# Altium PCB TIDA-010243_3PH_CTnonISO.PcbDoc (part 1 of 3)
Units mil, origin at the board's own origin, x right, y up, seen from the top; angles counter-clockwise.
Board outline 6131.89 x 7490.17 mil, 2 copper layers (Top Layer, Bottom Layer), stack 62 mil thick; 208 components, 218 nets, 747 pads, 147 vias.
Unrouted connection lines stored in the file: 258.
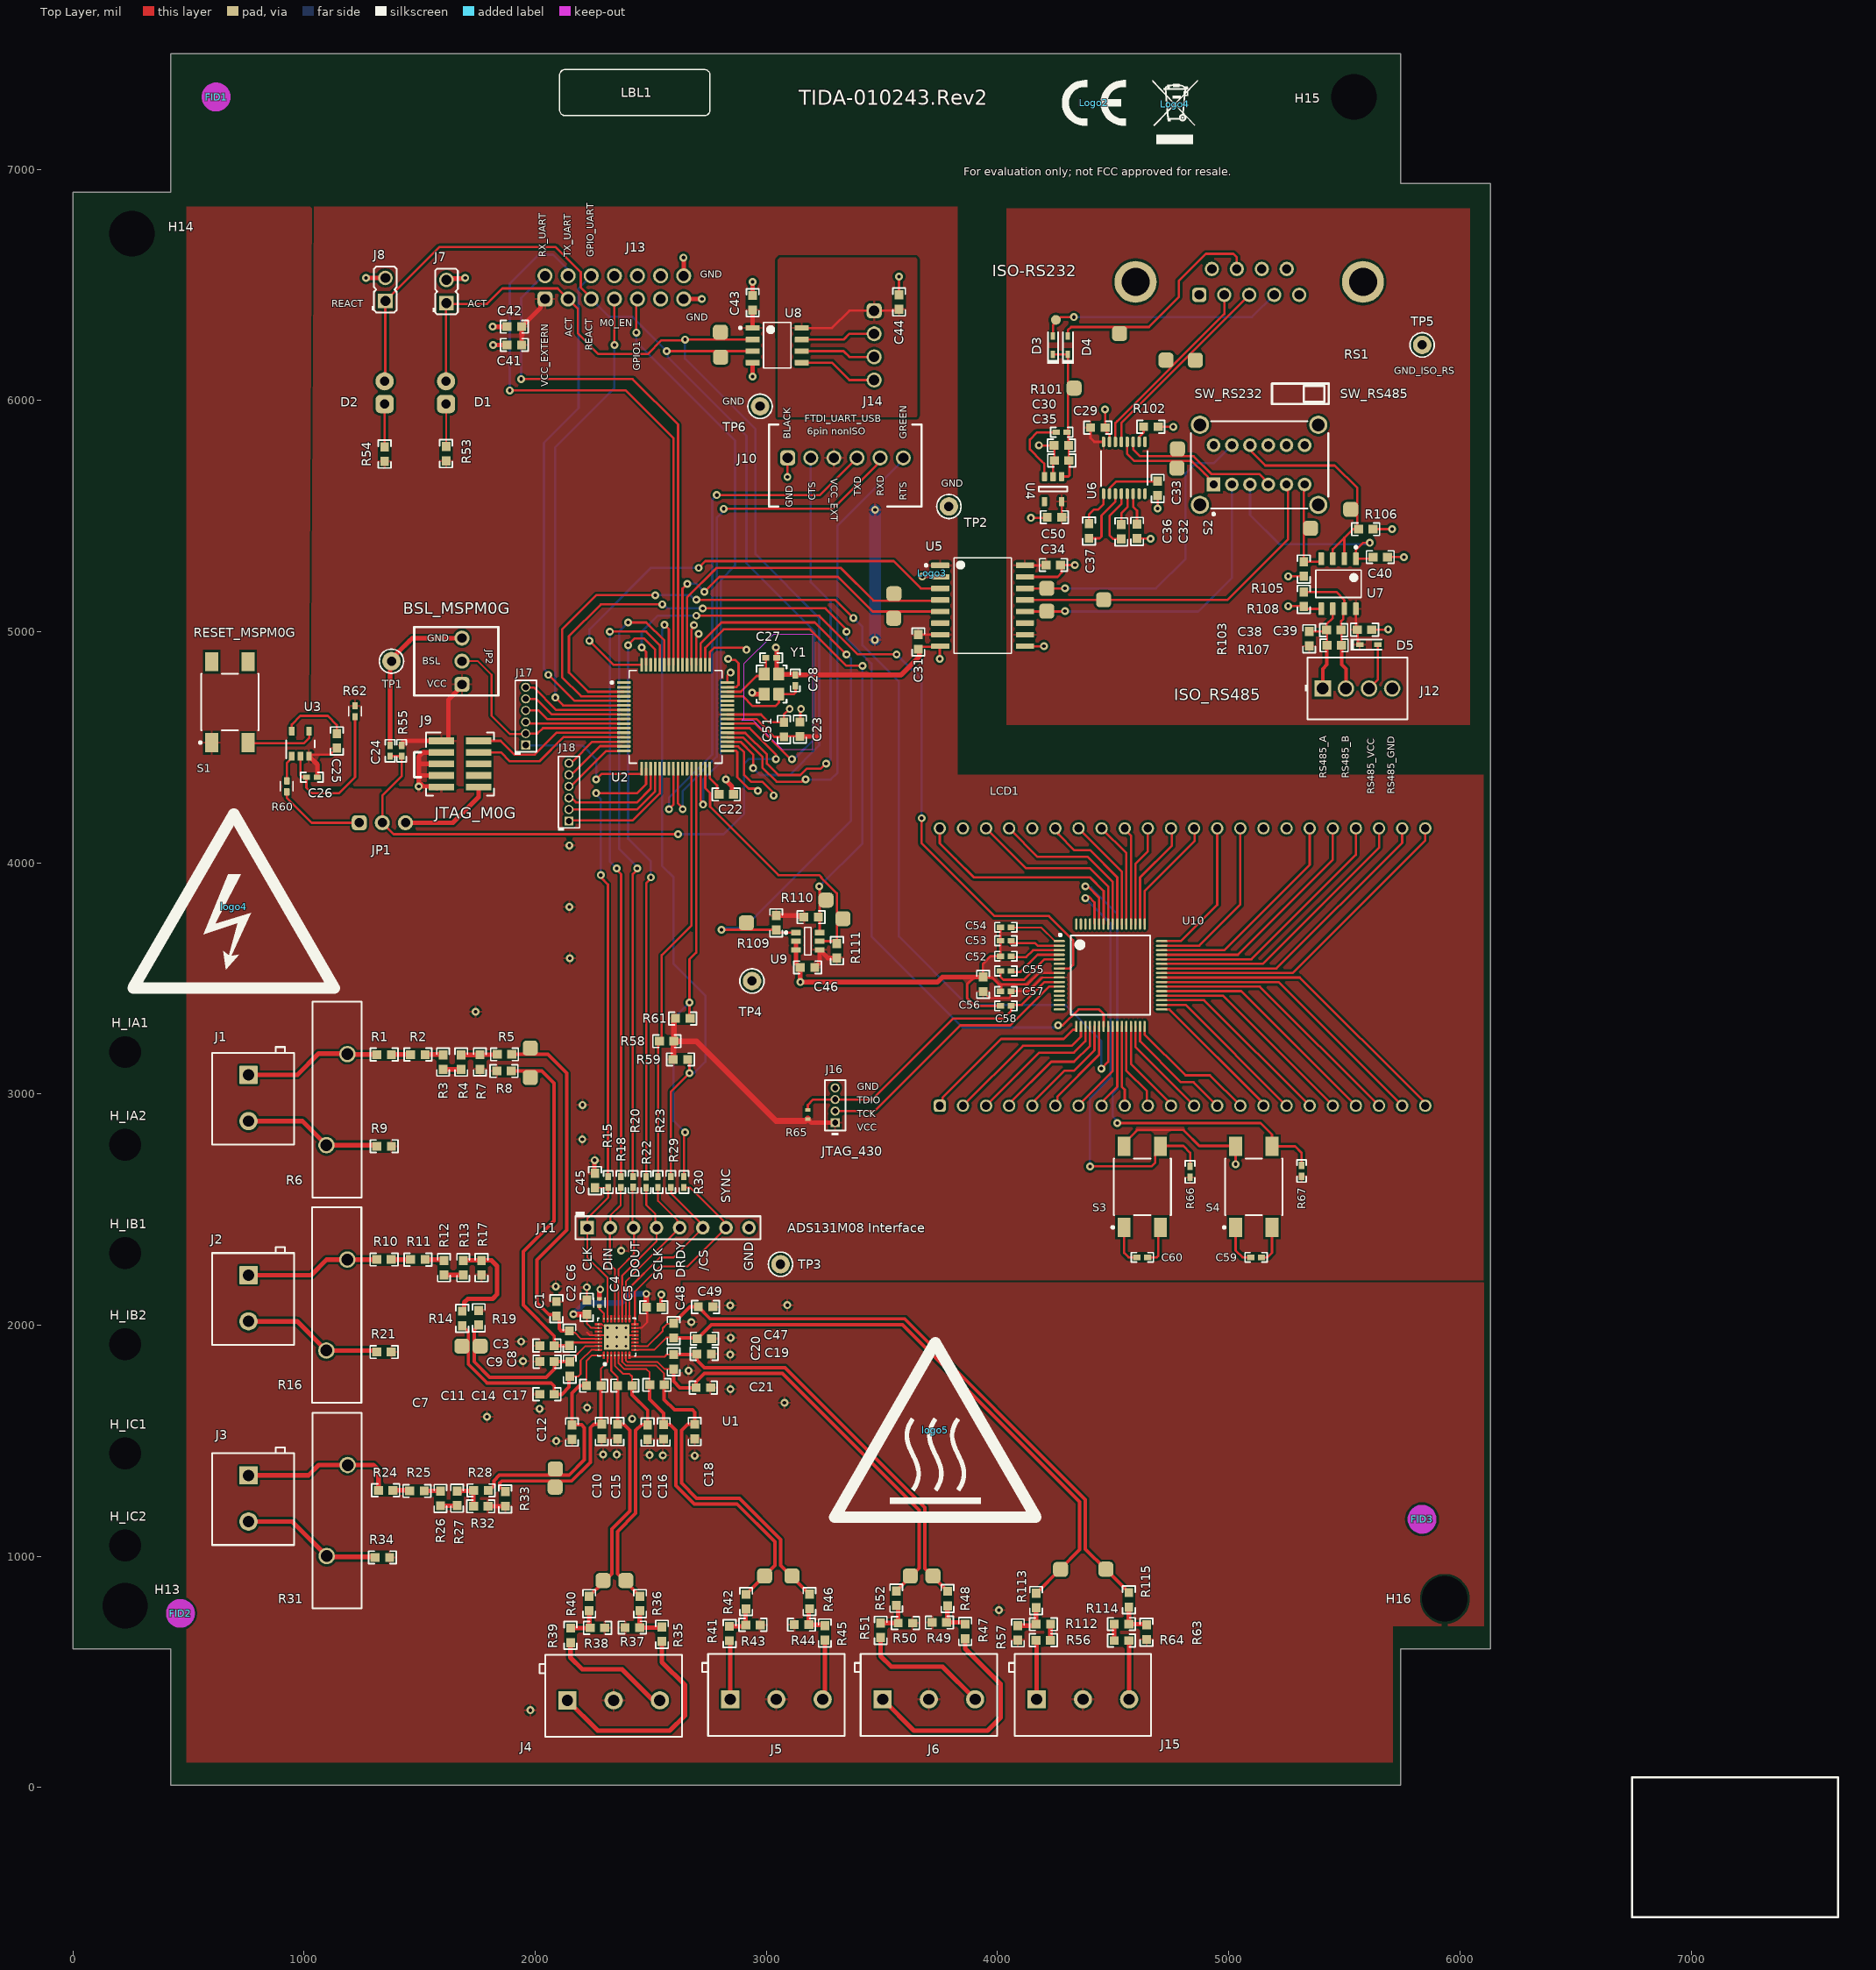
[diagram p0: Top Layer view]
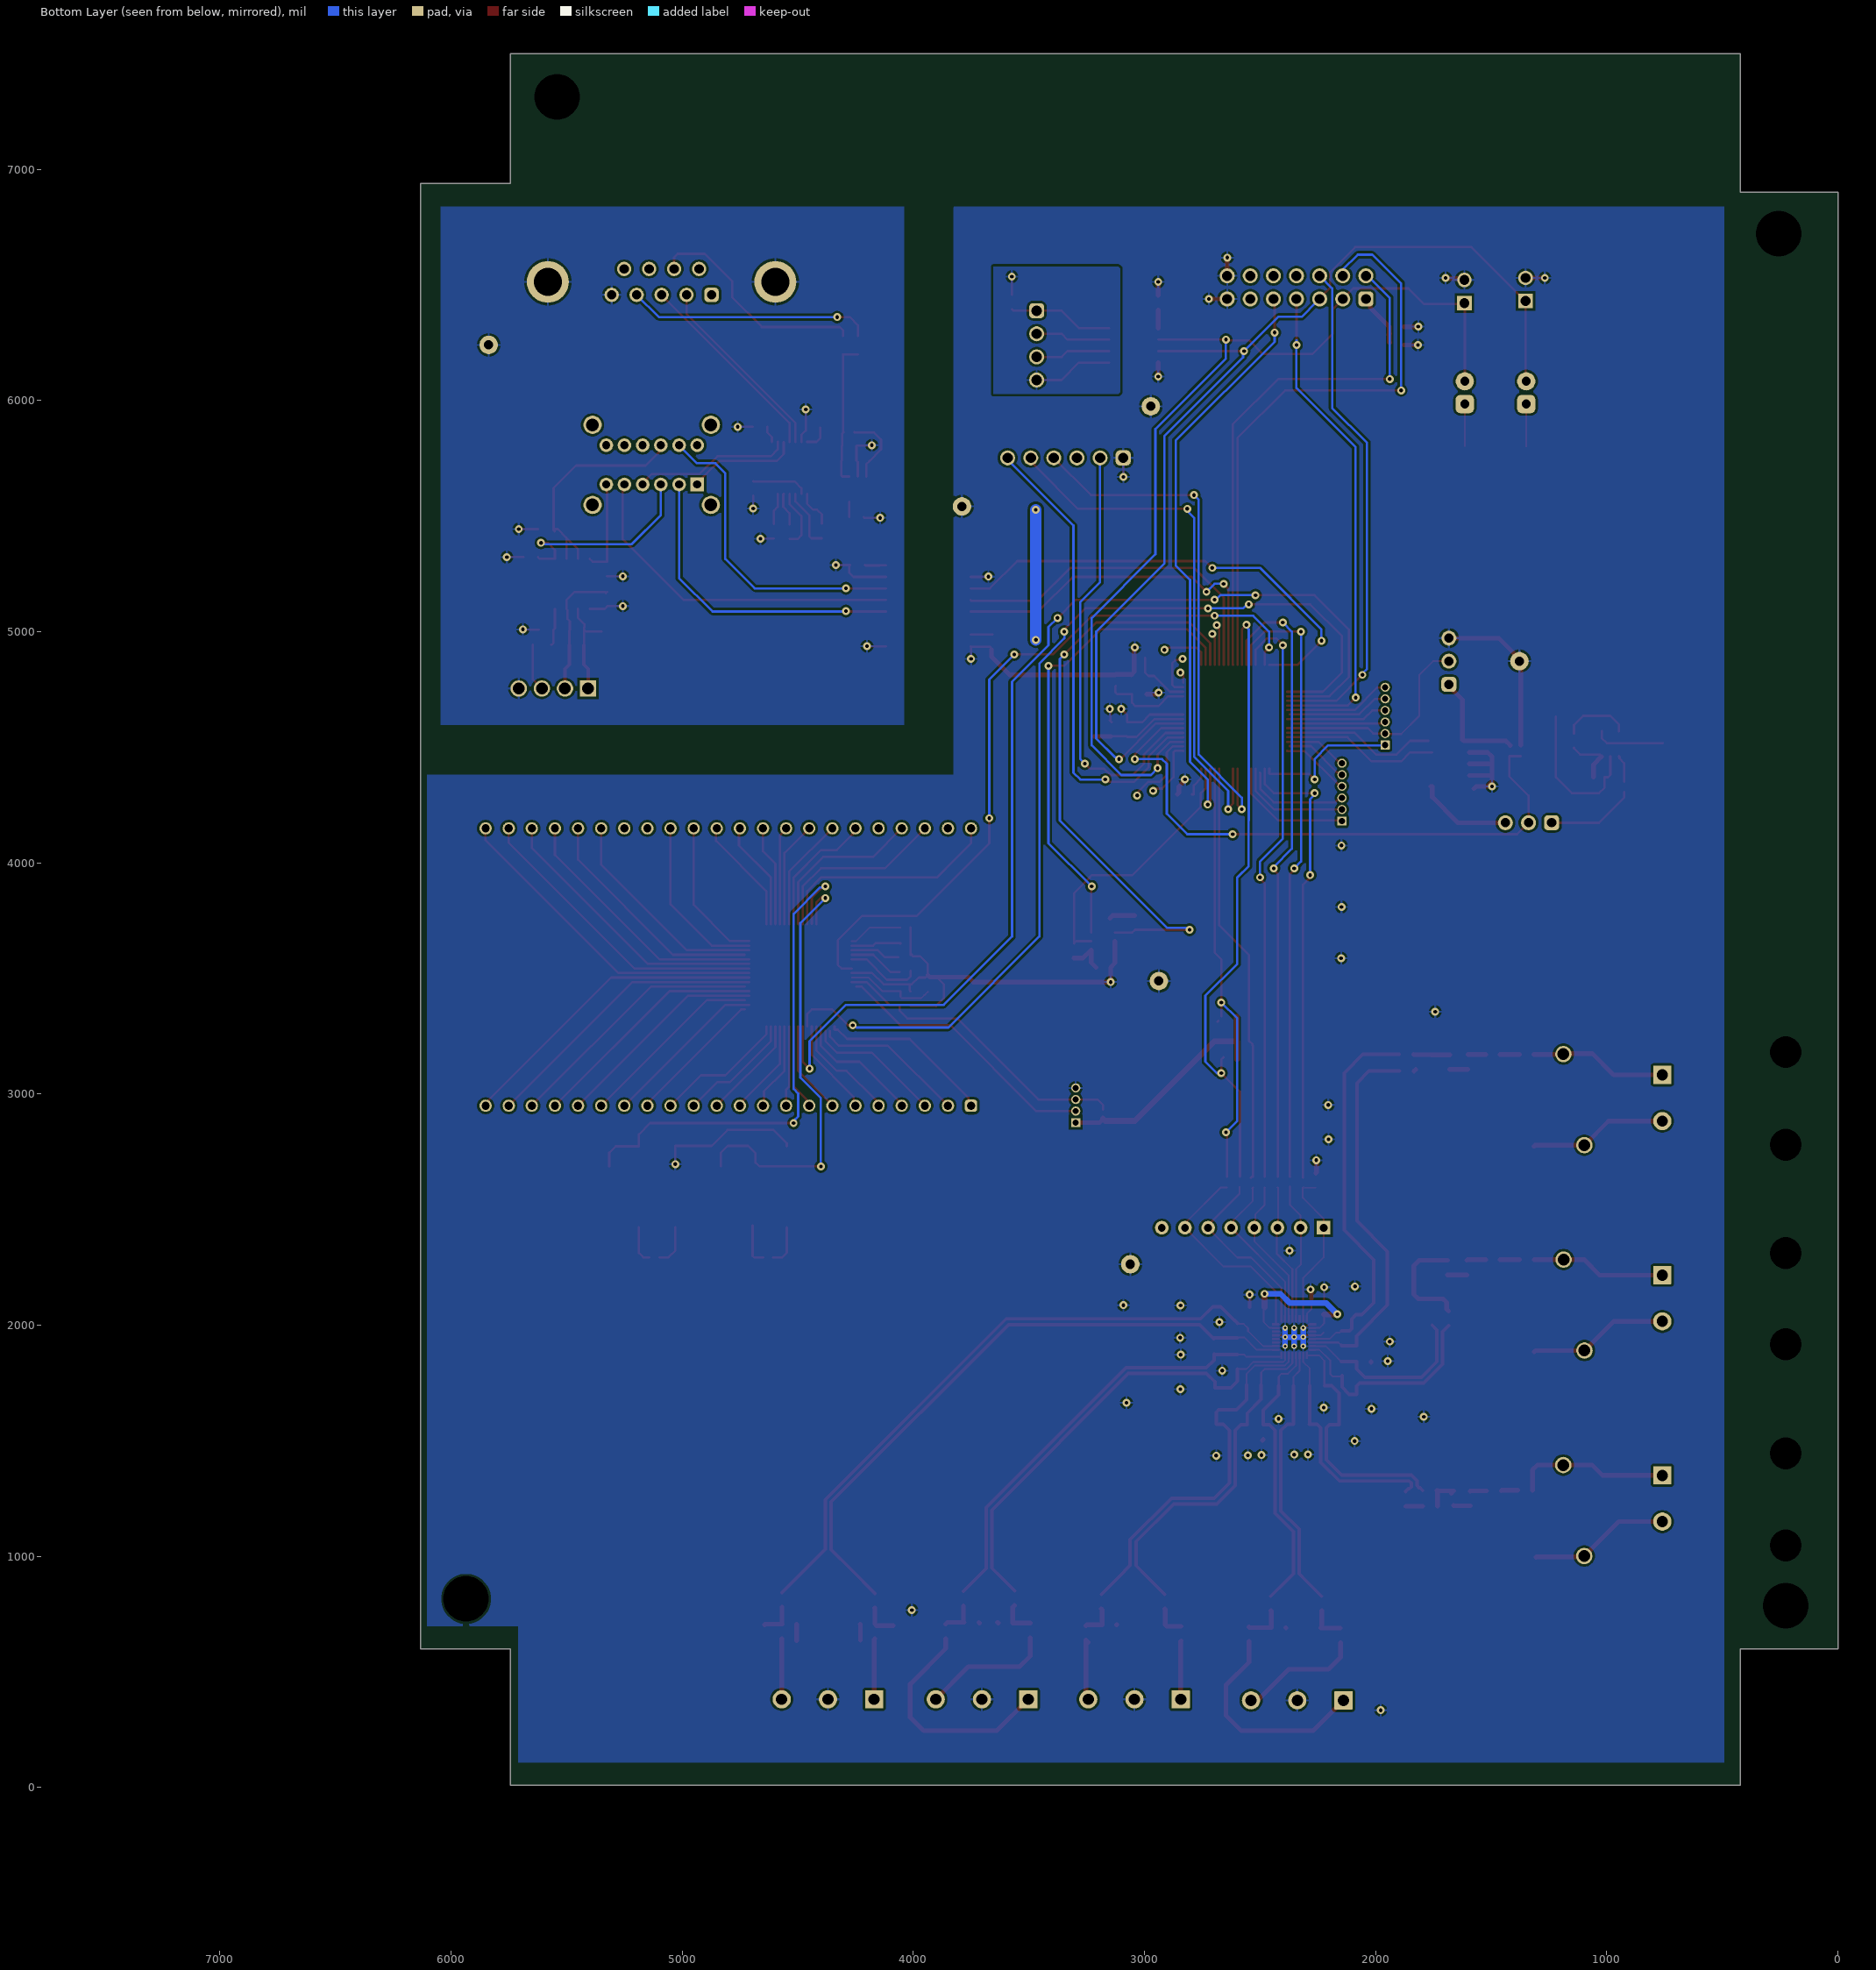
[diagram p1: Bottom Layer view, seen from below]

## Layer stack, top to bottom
Top Solder: solder mask 0.4, Solder Resist, Dk 3.5
Top Layer: signal copper 1.4
Dielectric1: core 59.2, FR-4 High Tg, Dk 4
Bottom Layer: signal copper 1.4
Bottom Solder: solder mask 0.4, Solder Resist, Dk 3.5

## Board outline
422.65,9.88 5742.63,9.83 5742.63,600.39 6131.89,600.39 6131.89,6938.98 5742.63,6938.98 5742.63,7500 422.65,7500 422.65,6899.61 0,6899.61 0,600.39 422.65,600.39

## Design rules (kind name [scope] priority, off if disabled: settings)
AcuteAngle [All] p1: minimum=4.50000000000000E+0001 checktracksonly=FALSE
AssemblyTestPointUsage [All] p1: valid=2
BoardOutlineClearance BoardOutlineClearance_MountingHoles [OnCopper and InComponentClass('Mounting Holes')] p1: gap=39.37 ignorepadtopadclearanceinfootprint=FALSE
BoardOutlineClearance BoardOutlineClearance_Poly [OnCopper and IsPoly] p2: gap=25 ignorepadtopadclearanceinfootprint=FALSE
BoardOutlineClearance [OnCopper and Not InComponentClass('Logo') and not InComponentClass('FiducialMark') and not InRegion(1000,500,4000,800) and not InPoly] p3: gap=40 ignorepadtopadclearanceinfootprint=FALSE
Clearance Clearance_Keepouts [((IsTrack Or IsArc) And Not InPoly) And IsFree and IsKeepOut vs ((IsTrack Or IsArc) And Not InPoly) And IsFree and IsKeepOut] p1: gap=0 ignorepadtopadclearanceinfootprint=FALSE
Clearance Clearance_Poly [InPolygon] p2: gap=10 ignorepadtopadclearanceinfootprint=TRUE
Clearance Clearance_FiducialMark [IsKeepOut and InComponentClass('FiducialMark') vs IsPad and InComponentClass('FiducialMark')] p3: gap=0 ignorepadtopadclearanceinfootprint=FALSE
Clearance [All] p4: gap=7.87 ignorepadtopadclearanceinfootprint=TRUE except(7: Track-Region; 7.5: Track-Track)
ComponentClearance ComponentClearance_THtoSMT_1 [InComponent('LCD1') vs InComponentClass('Top Side Components')] p1: gap=0 collisioncheckmode=3 verticalgap=0 showdistances=TRUE
ComponentClearance ComponentClearance_MountingHoles_FiducialMarks [InComponentClass('Mounting Holes') vs InComponentClass('FiducialMark')] p2: gap=50 collisioncheckmode=3 verticalgap=10 showdistances=FALSE
ComponentClearance ComponentClearance_Shunt [InComponentClass('Header') vs InComponentClass('Shunt')] p3: gap=0 collisioncheckmode=3 verticalgap=0 showdistances=FALSE
ComponentClearance ComponentClearance_Logo [InComponentClass('Logo')] p4: gap=30 collisioncheckmode=3 verticalgap=10 showdistances=FALSE
ComponentClearance ComponentClearance_ScrewToNut [(HasFootprint('NY PMS 440 0025 PH')) vs (HasFootprint('Keystone_1902C'))] p5: gap=5 collisioncheckmode=3 verticalgap=10 showdistances=FALSE
ComponentClearance ComponentClearance_MountingHoles [InComponentClass('Mounting Holes')] p6: gap=100 collisioncheckmode=3 verticalgap=100000 showdistances=FALSE
ComponentClearance ComponentClearance_SmallPassives [HasFootprint('0201*') or HasFootprint('0402*') or HasFootprint('0508') or HasFootprint('0603*') or HasFootprint('0612') or HasFootprint('0805*') or HasFootprint('0815*') or HasFootprint('0830*') or HasFootprint('1206*') or HasFootprint('1210*') or HasFootprint('1808*') or HasFootprint('1812*') or HasFootprint('1825*') or HasFootprint('2010*') or HasFootprint('2220*') or HasFootprint('2225*') or HasFootprint('2512*') or HasFootprint('2728*') or HasFootprint('3518*') vs HasFootprint('0201*') or HasFootprint('0402*') or HasFootprint('0508') or HasFootprint('0603*') or HasFootprint('0612') or HasFootprint('0805*') or HasFootprint('0815*') or HasFootprint('0830*') or HasFootprint('1206*') or HasFootprint('1210*') or HasFootprint('1808*') or HasFootprint('1812*') or HasFootprint('1825*') or HasFootprint('2010*') or HasFootprint('2220*') or HasFootprint('2225*') or HasFootprint('2512*') or HasFootprint('2728*') or HasFootprint('3518*')] p7: gap=14.96 collisioncheckmode=3 verticalgap=10 showdistances=FALSE
ComponentClearance ComponentClearance_THtoSMT [IsThruComponent vs IsSMTComponent] p8: gap=30 collisioncheckmode=3 verticalgap=30 showdistances=FALSE
ComponentClearance ComponentClearance_THtoTH [IsThruComponent vs IsThruComponent] p9: gap=20 collisioncheckmode=3 verticalgap=30 showdistances=FALSE
ComponentClearance [All] p10: gap=20 collisioncheckmode=3 verticalgap=10 showdistances=FALSE
DiffPairsRouting [All] p1: maxlimit=100 minlimit=10 mostfreqgap=10 toplayer_minwidth=15 toplayer_maxwidth=15 toplayer_prefwidth=15 bottomlayer_minwidth=15 bottomlayer_maxwidth=15 bottomlayer_prefwidth=15 maxuncoupledlength=1000
FabricationTestPointUsage TestPointUsage [All] p1: valid=2 allowmultiple=FALSE
FabricationTestpoint Testpoint [All] p1: side=3 testpointundercomponent=TRUE minsize=40 maxsize=100 preferedsize=60 minholesize=0 maxholesize=40 preferedholesize=32 testpointgrid=1 allowsidetop=TRUE allowsidebottom=TRUE usegrid=TRUE gridtolerance=0.01
FanoutControl Fanout_LCC [IsLCC] p1: bgadir=Out bgaviamode=Centered fanoutstyle=Auto fanoutdirection=Alternating viagrid=1 // Fanout_LCC (Default Rule)
FanoutControl Fanout_BGA [IsBGA] p2: bgadir=Out bgaviamode=Centered fanoutstyle=Auto fanoutdirection=Alternating viagrid=1 // Fanout_BGA (Default Rule)
FanoutControl Fanout_Default [All] p4: bgadir=Out bgaviamode=Centered fanoutstyle=Auto fanoutdirection=Alternating viagrid=1 // Fanout_Default (Default Rule)
FanoutControl Fanout_Small [(CompPinCount < 5)] p5: bgadir=Out bgaviamode=Centered fanoutstyle=Auto fanoutdirection=OutThenIn viagrid=1 // Fanout_Small (Default Rule)
Height [All] p1: minheight=0 maxheight=1100 prefheight=500
HoleSize [All] p1: absolutevalues=TRUE maxlimit=251 minlimit=7.87 maxpercent=80.000 minpercent=20.000
MinimumAnnularRing MinimumAnnularRing_ThermalPadVias [IsVia and InAnyComponent] p1: minimumring=5.91
MinimumAnnularRing [All] p2: minimumring=5.9
MinimumSolderMaskSliver MinimumSolderMaskSliver_Logo [InComponentClass('Logo') vs InComponentClass('Logo')] p1: minsoldermaskwidth=0.7
MinimumSolderMaskSliver [All] p2: minsoldermaskwidth=3.94
PlaneConnect [All] p1: planeconnectstyle=Relief reliefexpansion=10 reliefentries=4 reliefconductorwidth=10 reliefairgap=10
PolygonConnect [All] p1: connectstyle=Relief reliefconductorwidth=10 reliefentries=4 polygonreliefangle="90 Angle" airgapwidth=10
RoutingVias ThermalPadVias [IsVia and InAnyComponent] p1: holewidth=7.87 width=19.68 viastyle="Through Hole" minholewidth=7.87 minwidth=19.68 maxholewidth=12.99 maxwidth=23.62
RoutingVias [All] p2: holewidth=16 width=34 viastyle="Through Hole" minholewidth=7.87 minwidth=24 maxholewidth=40 maxwidth=65
SilkToBoardRegionClearance [Not ((IsComment or IsDesignator) And (Hide <> 'False')) and not InRegion(1000,500,4000,800)] p1:
SilkToSilkClearance SilkToSilkClearance_Pb-FreeLogo [(HasFootprint('Pb-Free_Overlay_Medium') OR HasFootprint('Pb-Free_Overlay_Small')) vs (HasFootprint('Pb-Free_Overlay_Medium') OR HasFootprint('Pb-Free_Overlay_Small'))] p1: silktosilkclearance=0
SilkToSilkClearance [All] p2: silktosilkclearance=3.94
SilkToSolderMaskClearance SilkToComponentPadClearance [(IsPad or IsFill or IsRegion) and InAnycomponent] p1: minsilkscreentomaskgap=5 clearancetoexposedcopper=TRUE
SilkToSolderMaskClearance "Silk to Solder Mask Opening" [All] p2: minsilkscreentomaskgap=3.94 clearancetoexposedcopper=FALSE
SolderMaskExpansion [All] p1: expansion=1.97 istentingtop=FALSE
UnRoutedNet [All] p1: checkbadconnections=TRUE
Width [All] p1: maxlimit=100 minlimit=6 preferedwidth=10 checkconnectedcopper=TRUE
13 further rules are at their usual default settings.

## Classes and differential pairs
component class TIDA_010243-MCU: C22 C23 C24 C24_1 C25 C25_1 C26 C26_1 C27 C28 C51 C52 C53 C54 C55 C56 C57 C58 C59 C60 D1 D2 J7 J8 J9 J16 J17 J18 JP1 JP1_1 JP2 LCD1 R53 R54 R55 R55_1 R60 R62 R62_1 R65 R66 R67 S1 S3 S4 TP1 TP2 U2 U3 U3_1 U10 Y1
component class TIDA-010243_Interfaces: C29 C30 C31 C32 C33 C34 C35 C36 C37 C38 C39 C40 C41 C42 C43 C44 C50 D3 D4 D5 J10 J12 J13 J14 R101 R102 R103 R105 R106 R107 R108 RS1 S2 TP5 TP6 U4 U5 U6 U7 U8
component class Header: J7 J8 J10 J11 J13 J14 J16 J17 J18 JP1 JP2
component class TIDA-010243-AFE: C1 C2 C3 C4 C5 C6 C7 C8 C9 C10 C11 C12 C13 C14 C15 C16 C17 C18 C19 C20 C21 C45 C46 C47 C48 C49 H_IA1 H_IA2 H_IB1 H_IB2 H_IC1 H_IC2 J1 J2 J3 J4 J5 J6 J11 J15 R1 R2 R3 R4 R5 R6 R7 R8 R9 R10 R11 R12 R13 R14 R15 R16 R17 R18 R19 R20 R21 R22 R23 R24 R25 R26 R27 R28 R29 R30 R31 R32 R33 R34 R35 R36 R37 R38 R39 R40 R41 R42 R43 R44 R45 R46 R47 R48 R49 R50 R51 R52 R56 R57 R58 R59 R61 R63 R64 R109 R110 R111 R112 R113 R114 R115 TP3 TP4 U1 U9
component class TIDA-010243_Hardware: FID1 FID2 FID3 H13 H14 H15 H16 LBL1 Logo2 Logo3 Logo4 logo4 logo5
component class FiducialMark: FID1 FID2 FID3
component class Label: LBL1

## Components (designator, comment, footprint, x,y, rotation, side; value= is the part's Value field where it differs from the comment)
C1 "GCM1885C2A100JA16D" 0603 2091.78,2071.09 r90 top value=10pF
C2 "CGA3EANP02A682J080AC" 0603 2147.74,1943.92 r270 top value=6800pF
C3 "GCM1885C2A100JA16D" 0603 2050.7,1911.7 r0 top value=10pF
C4 "CGA2B2X7R1C224K050BE" FP-CGA2B2X7R1C224K050BE_0402-MFG 2277.32,2098.52 r90 top value=220nF
C5 "CGA3E1X7R1C105K080AC" 0603 2512.94,2077.77 r0 top value=1uF
C6 "CGA3E1X7R1C105K080AC" 0603 2222.82,2077.77 r90 top value=1uF
C7 "GCM1885C2A100JA16D" 0603 2050.7,1701.33 r180 top value=10pF
C8 "CGA3EANP02A682J080AC" 0603 2149.28,1810.11 r90 top value=6800pF
C9 "GCM1885C2A100JA16D" 0603 2051.02,1842.22 r0 top value=10pF
C10 "GCM1885C2A100JA16D" 0603 2158.73,1537.8 r270 top value=10pF
C11 "CGA3EANP02A682J080AC" 0603 2253.08,1738.24 r0 top value=6800pF
C12 "GCM1885C2A100JA16D" 0603 2287.45,1540.5 r90 top value=10pF
C13 "GCM1885C2A100JA16D" 0603 2485.99,1537.8 r270 top value=10pF
C14 "" 0603 2387.49,1738.7 r180 top value=6800pF
C15 "GCM1885C2A100JA16D" 0603 2355.56,1540.01 r90 top value=10pF
C16 "GCM1885C2A100JA16D" 0603 2555.37,1538.64 r270 top value=10pF
C17 "" 0603 2526.39,1742.21 r0 top value=6800pF
C18 "GCM1885C2A100JA16D" 0603 2689.65,1540.01 r90 top value=10pF
C19 "GCM1885C2A100JA16D" 0603 2730.62,1875.63 r0 top value=10pF
C20 "" 0603 2598.46,1841.6 r270 top value=6800pF
C21 "GCM1885C2A100JA16D" 0603 2727.06,1729.88 r180 top value=10pF
C22 "GRM188R61A474KA61D" 0603 2826.26,4296.28 r180 top value=0.47uF
C23 "GRM188R61A106KAALD" 0603 3144.88,4577.86 r270 top value=10uF
C24 "GRM155R61A102KA01D" 0402 1372.05,4484.65 r90 top value=1000pF
C25 "GRM188R71C334KA01D" 0603 1141.73,4527.56 r90 top value=0.33uF
C26 "GCM155R71H104KE02D" 0402 1033.46,4370.08 r180 top value=0.1uF
C27 "GRM1555C1H150JA01D" 0402 3021,4886.51 r0 top value=15pF
C28 "GRM1555C1H150JA01D" 0402 3124.74,4788.97 r90 top value=15pF
C29 "CGA3E2X8R1E104K080AA" 0603 4433.38,5882.58 r180 top value=0.1uF
C30 "GRT188R61H225KE13D" 0603 4275.9,5805.13 r180 top value=2.2uF
C31 "C0603X104K3RACTU" 0603 3657.22,4955.4 r270 top value=0.1uF
C32 "CGA3E2X8R1E104K080AA" 0603 4603.05,5433.56 r90 top value=0.1uF
C33 "CGA3E2X8R1E104K080AA" 0603 4692.56,5619.52 r90 top value=0.1uF
C34 "C0603X104K3RACTU" 0603 4241.17,5288.08 r0 top value=0.1uF
C35 "CGA3E1X7R1E105M080AC" 0603 4277.22,5740.02 r180 top value=1uF
C36 "CGA3E2X8R1E104K080AA" 0603 4535.09,5431.85 r270 top value=0.1uF
C37 "CGA3E2X8R1E104K080AA" 0603 4395.39,5435.04 r90 top value=0.1uF
C38 "CGA3E2C0G1H100D080AA" 0603 5454.18,5006.69 r0 top value=10pF
C39 "CGA3E2X8R1E104K080AA" 0603 5587.29,5008.07 r0 top value=0.1uF
C40 "CGA3E2C0G1H100D080AA" 0603 5655.26,5322.55 r180 top value=10pF
C41 "C0603X104K3RACTU" 0603 1909.45,6240.16 r180 top value=0.1uF
C42 "C0603C105K3RACTU" 0603 1909.45,6318.9 r0 top value=1uF
C43 "CGA3E2X8R1E104K080AA" 0603 2940.24,6422.6 r90 top value=0.1uF
C44 "CGA3E2X8R1E104K080AA" 0603 3573.51,6425.79 r90 top value=0.1uF
C45 "GCM1885C2A100JA16D" 0603 2258.61,2625.54 r90 top value=10pF
C46 "C0603X104K3RACTU" 0603 3177.79,3547.71 r180 top value=0.1uF
C47 "GCM1885C2A100JA16D" 0603 2732.01,1941.43 r0 top value=10pF
C48 "" 0603 2598.61,1976.89 r90 top value=6800pF
C49 "GCM1885C2A100JA16D" 0603 2736.5,2079.3 r180 top value=10pF
C50 "GRT188R61H225KE13D" 0603 4245.72,5495.02 r180 top value=2.2uF
C51 "C0603C105K3RACTU" 0603 3075.57,4576.37 r90 top value=1uF
C52 "GCM155R71A104KA55D" 0402 4035.43,3596 r0 top value=0.1uF
C53 "GCM155R71A104KA55D" 0402 4035.43,3663 r0 top value=0.1uF
C54 "GCM155R71A104KA55D" 0402 4035.43,3721.08 r0 top value=0.1uF
C55 "GCM155R71A104KA55D" 0402 4035.43,3532 r180 top value=0.1uF
C56 "GRM188R61A106ME69D" 0603 3937.01,3474.41 r90 top value=10uF
C57 "GCM155R71A104KA55D" 0402 4035.43,3444 r180 top value=0.1uF
C58 "885012205044" 0402 4035.43,3381.03 r180 top value=1000pF
C59 "C0402C104K4RACAUTO" 0402 5118.11,2293.31 r180 top value=0.1uF
C60 "C0402C104K4RACAUTO" 0402 4625.98,2293.31 r180 top value=0.1uF
D1 "SLR-342VC3F" SLR-342_Red 1614.17,6033.46 r90 top value=Red
D2 "SLR-342VC3F" SLR-342_Red 1348.43,6033.46 r90 top value=Red
D3 "1N4148WT" Fairchild_SOD-523F 4239.31,6238.91 r90 top value=75V
D4 "1N4148WT" Fairchild_SOD-523F 4303.9,6238.81 r90 top value=75V
D5 "1N4148WT" Fairchild_SOD-523F 5605.99,4944.03 r0 top value=75V
FID1 "Fiducial" Fiducial10-30 619.55,7312.46 r0 top
FID2 "Fiducial" Fiducial10-30 464.98,753.59 r0 top
FID3 "Fiducial" Fiducial10-30 5836.09,1160.89 r0 top
H13 "5MM HOLE" 5MM_HOLE 225.85,787.4 r0 top
H14 "5MM HOLE" 5MM_HOLE 255.85,6721.91 r0 top
H15 "5MM HOLE" 5MM_HOLE 5540.81,7312.46 r0 top
H16 "5MM HOLE" 5MM_HOLE 5934.51,816.4 r0 top
H_IA1 "3.5 MM HOLE" 3_5MM_HOLE 225.85,3181.54 r0 top
H_IA2 "3.5 MM HOLE" 3_5MM_HOLE 225.85,2780.35 r0 top
H_IB1 "3.5 MM HOLE" 3_5MM_HOLE 225.85,2311.91 r0 top
H_IB2 "3.5 MM HOLE" 3_5MM_HOLE 225.85,1918.21 r0 top
H_IC1 "3.5 MM HOLE" 3_5MM_HOLE 225.85,1445.92 r0 top
H_IC2 "3.5 MM HOLE" 3_5MM_HOLE 225.85,1047.32 r0 top
J1 "ED120/2DS" On-Shore_ED120_2DS 759.85,2982.84 r270 top
J2 "ED120/2DS" On-Shore_ED120_2DS 759.85,2116.74 r270 top
J3 "ED120/2DS" On-Shore_ED120_2DS 759.85,1250.65 r270 top
J4 "ED120/3DS" On-Shore_ED120_3DS 2339.06,377.39 r0 top
J5 "ED120/3DS" On-Shore_ED120_3DS 3043.06,381.89 r0 top
J6 "ED120/3DS" On-Shore_ED120_3DS 3702.74,381.89 r0 top
J7 "961102-6404-AR" 3M_961102-6404-AR 1615.88,6471.1 r90 top
J8 "961102-6404-AR" 3M_961102-6404-AR 1351.46,6479.86 r90 top
J9 "FTSH-105-01-L-DV-K" Samtec_FTSH-105-01-x-DV-K 1674.61,4427.56 r0 top
J10 "61300611121" WURTH_61300611121 3341.88,5751.41 r0 top
J11 "800-10-008-10-001000" Mill-Max_800-10-008-10-001000 2574.8,2421.26 r0 top
J12 "OSTVN04A150" On-Shore_OSTVN04A150 5556.61,4753.94 r0 top
J13 "61301421121" Wurth_61301421121 2342.23,6488.92 r90 top
J14 "61300411121" WURTH_61300411121 3466.1,6238.18 r270 top
J15 "ED120/3DS" On-Shore_ED120_3DS 4369.05,381.89 r0 top
J16 "850-10-004-10-001101" Preci-dip_850-xx-004-10-001101 3297.24,2951.32 r90 top
J17 "GRPB061VWVN-RC" Sullins_GRPB061VWVN-RC 1958.66,4634.25 r90 top
J18 "GRPB061VWVN-RC" Sullins_GRPB061VWVN-RC 2145.67,4305.71 r90 top
JP1 "TSW-103-07-G-S" TSW-103-07-G-S 1338.58,4173.23 r0 top
JP2 "TSW-103-07-G-S" TSW-103-07-G-S 1683.07,4872.05 r90 top
LBL1 "THT-14-423-10" Label_650x200 2430.59,7331.61 r0 top
LCD1 "FH-1152P" ADKOM_FH-1152P 4800,3549.21 r90 top locked
Logo2 "CE Mark" CE_Mark_5mm 4416.46,7287.02 r0 top
Logo3 "FCC disclaimer" FCC_disclaimer 3715.81,5252.46 r0 top
logo4 "DANGER HIGH VOLTAGE" IEC_HighVoltage_Large 696,3809.77 r0 top
Logo4 "WEEE logo" WEEE_Minimum 4766.46,7281.34 r0 top
logo5 "CAUTION HOT SURFACE" IEC_HotSurface_Large 3730.31,1545.28 r0 top
R1 "ERJ-3GEY0R00V" 0603 1346.46,3170.66 r0 top value=0
R2 "RG1608P-334-B-T5" 0603 1492.45,3170.66 r180 top value=330k
R3 "RG1608P-334-B-T5" 0603 1601.1,3138.33 r90 top value=330k
R4 "RG1608P-334-B-T5" 0603 1679.76,3137.88 r90 top value=330k
R5 "RT0603DRD071KL" 0603 1866.97,3171.41 r0 top value=1.00k
R6 "B72220S0271K101" Epcos_B72220S0271K101 1142.31,2975.6 r270 top locked value=275VAC
R7 "RT0603DRE07750RL" 0603 1760.64,3138.45 r90 top value=750
R8 "RT0603DRD071KL" 0603 1865.01,3099.32 r0 top value=1.00k
R9 "ERJ-3GEY0R00V" 0603 1346.46,2774.1 r0 top value=0
R10 "ERJ-3GEY0R00V" 0603 1345.92,2284.06 r0 top value=0
R11 "RG1608P-334-B-T5" 0603 1492.45,2284.06 r180 top value=330k
R12 "RG1608P-334-B-T5" 0603 1604.95,2248.89 r90 top value=330k
R13 "RG1608P-334-B-T5" 0603 1688.42,2248.89 r90 top value=330k
R14 "RT0603DRD071KL" 0603 1684.11,2029.35 r270 top value=1.00k
R15 "CRCW040233R0JNED" 0402 2315.5,2619.24 r90 top value=33
R16 "B72220S0271K101" Epcos_B72220S0271K101 1141.73,2087.17 r270 top value=275VAC
R17 "RT0603DRE07750RL" 0603 1767.32,2248.89 r90 top value=750
R18 "CRCW040233R0JNED" 0402 2370.39,2619.06 r90 top value=33
R19 "RT0603DRD071KL" 0603 1755.17,2032.07 r270 top value=1.00k
R20 "CRCW040233R0JNED" 0402 2423.24,2619.59 r90 top value=33
R21 "ERJ-3GEY0R00V" 0603 1345.92,1884.44 r0 top value=0
R22 "CRCW040233R0JNED" 0402 2479.52,2618.11 r90 top value=33
R23 "CRCW040233R0JNED" 0402 2530.9,2619.24 r90 top value=33
R24 "ERJ-3GEY0R00V" 0603 1353.02,1286 r0 top value=0
R25 "RG1608P-334-B-T5" 0603 1488.32,1283.26 r180 top value=330k
R26 "RG1608P-334-B-T5" 0603 1589.83,1250.74 r90 top value=330k
R27 "RG1608P-334-B-T5" 0603 1662.2,1251.67 r90 top value=330k
R28 "RT0603DRD071KL" 0603 1765.45,1285.54 r0 top value=1.00k
R29 "CRCW04020000Z0ED" 0402 2586.46,2619.24 r90 top value=0
R30 "CRCW040233R0JNED" 0402 2642.94,2619.24 r90 top value=33
R31 "B72220S0271K101" Epcos_B72220S0271K101 1143.02,1198.34 r270 top value=275VAC
R32 "RT0603DRE07750RL" 0603 1764.28,1216.8 r180 top value=750
R33 "RT0603DRD071KL" 0603 1870.12,1248.7 r90 top value=1.00k
R34 "ERJ-3GEY0R00V" 0603 1338.71,995.75 r0 top value=0
R35 "ERJ-3GEY0R00V" 0603 2547.8,663.26 r90 top value=0
R36 "RT0603DRD072KL" 0603 2453.21,795.93 r90 top value=2.00k
R37 "CRCW06036R49FKEA" 0603 2420.09,692.35 r0 top value=6.49
R38 "CRCW06036R49FKEA" 0603 2269.13,691.19 r0 top value=6.49
R39 "ERJ-3GEY0R00V" 0603 2152.66,658.47 r90 top value=0
R40 "RT0603DRD072KL" 0603 2233.37,795.93 r90 top value=2.00k
R41 "ERJ-3GEY0R00V" 0603 2840.32,666.33 r90 top value=0
R42 "RT0603DRD072KL" 0603 2912.23,804.47 r90 top value=2.00k
R43 "CRCW06036R49FKEA" 0603 2941.64,703.96 r180 top value=6.49
R44 "CRCW06036R49FKEA" 0603 3151.62,704.69 r180 top value=6.49
R45 "ERJ-3GEY0R00V" 0603 3252.6,668.88 r90 top value=0
R46 "RT0603DRD072KL" 0603 3186.49,804.89 r90 top value=2.00k
R47 "ERJ-3GEY0R00V" 0603 3859.78,675.42 r90 top value=0
R48 "RT0603DRD072KL" 0603 3783.4,817.93 r90 top value=2.00k
R49 "CRCW06036R49FKEA" 0603 3747.96,714.34 r0 top value=6.49
R50 "CRCW06036R49FKEA" 0603 3601.32,711.59 r0 top value=6.49
R51 "ERJ-3GEY0R00V" 0603 3493.96,680.18 r90 top value=0
R52 "RT0603DRD072KL" 0603 3561.94,819.06 r90 top value=2.00k
R53 "RC0603FR-07100RL" 0603 1614.17,5769.68 r270 top value=100
R54 "RC0603FR-07100RL" 0603 1348.43,5767.72 r270 top value=100
R55 "CRCW040247K0JNED" 0402 1422.05,4484.65 r90 top value=47k
R56 "ERJ-3GEY0R00V" 0603 4197.44,637.49 r0 top value=0
R57 "CRCW06036R49FKEA" 0603 4087.79,669.21 r90 top value=6.49
R58 "CRCW060310K0FKEA" 0603 2568.9,3228.35 r180 top value=10.0k
R59 "CRCW0603100KFKEA" 0603 2627.95,3149.61 r180 top value=100k
R60 "CR0402-10W-000T" FP-CR0402-10W-000T_0402-MFG 925.2,4330.71 r90 top value=0uΩ
R61 "CRCW0603100KFKEA" 0603 2637.8,3326.77 r180 top value=100k
R62 "CR0402-10W-000T" FP-CR0402-10W-000T_0402-MFG 1220.47,4655.51 r270 top value=0uΩ
R63 "CRCW06036R49FKEA" 0603 4644.07,672.24 r270 top value=6.49
R64 "ERJ-3GEY0R00V" 0603 4535.72,636.12 r180 top value=0
R65 "CRCW040247K0JNED" 0402S 3179.13,2911.95 r270 top value=47k
R66 "CRCW0402100KFKED" 0402 4832.68,2663.39 r270 top value=100k
R67 "CRCW0402100KFKED" 0402 5314.96,2667.32 r270 top value=100k
R101 "RC0402JR-070RL" 0402 4277.33,5862.63 r180 top value=0
R102 "CRCW06034K70JNEA" 0603 4662.75,5885.87 r180 top value=4.7k
R103 "CRCW0603100KJNEA" 0603 5347.55,4969.19 r270 top value=100k
R105 "CRCW06034K70JNEA" 0603 5324.32,5270.73 r270 top value=4.7k
R106 "CRCW06034K70JNEA" 0603 5592.31,5443.32 r0 top value=4.7k
R107 "RT0603DRE07120RL" 0603 5456.13,4940.64 r180 top value=120
R108 "CRCW0603100KJNEA" 0603 5324.56,5139.97 r90 top value=100k
R109 "RT0603DRD072KL" 0603 3042.19,3740.55 r90 top value=2.00k
R110 "RT0603DRD072KL" 0603 3192.91,3765.1 r180 top value=2.00k
R111 "RT0603DRD072KL" 0603 3304.83,3619.89 r270 top value=2.00k
R112 "ERJ-3GEY0R00V" 0603 4197.78,706.91 r180 top value=0
R113 "RT0603DRD072KL" 0603 4166.64,809.13 r90 top value=2.00k
R114 "ERJ-3GEY0R00V" 0603 4535.72,707.16 r0 top value=0
R115 "RT0603DRD072KL" 0603 4568.05,812.14 r90 top value=2.00k
RS1 "2-5747706-0" TE_2-5747706-0 5088.63,6512.69 r180 top
S1 "MJTPSMWBTR" SW_MJTPSMWB 679.13,4694.88 r90 top
S2 "1825264-1" SW_1825264-1 5131.37,5721.32 r90 top locked
S3 "MJTPSMWBTR" SW_MJTPSMWB 4625.98,2598.43 r90 top
S4 "MJTPSMWBTR" SW_MJTPSMWB 5108.27,2598.43 r90 top
TP1 "5000" Keystone5000 1377.95,4872.05 r0 top
TP2 "5000" Keystone5000 3789.37,5541.34 r90 top
TP3 "5000" Keystone5000 3061.02,2263.78 r90 top
TP4 "5000" Keystone5000 2937.56,3488.74 r90 top
TP5 "5000" Keystone5000 5836.61,6240.16 r90 top
TP6 "5000" Keystone5000 2972.44,5974.41 r90 top
U1 "ADS131M08IRSNR" RSN0032B-MFG 2352.36,1948.82 r90 top
U2 "MSPM0G1507SPM" PM0064A-MFG 2607.38,4631.67 r0 top locked
U3 "TPS3840DL20DBVR" DBV0005A_N 984.25,4515.41 r90 top locked
U4 "TPS70933DBVR" DBV0005A_N 4239.89,5616.57 r270 top
U5 "ISO6731DWR" DW0016A-MFG 3935.14,5111.9 r0 top locked
U6 "TRS3232ECPW" PW0016A_L 4547.88,5708.53 r90 top
U7 "THVD1400D" D0008B-MFG 5474.99,5206.7 r270 top
U8 "ISO6720BDR" D0008A-MFG 3046.54,6238.18 r0 top
U9 "TMAG5273A2QDBVR" DBV0006A-MFG 3179.13,3660.89 r0 top
U10 "MSP430FR4133IPMR" PM0064A_L 4488.19,3513.78 r0 top locked
Y1 "FA-238 16.3840MB-K" Epson_FA-238 3022.17,4772.81 r0 top

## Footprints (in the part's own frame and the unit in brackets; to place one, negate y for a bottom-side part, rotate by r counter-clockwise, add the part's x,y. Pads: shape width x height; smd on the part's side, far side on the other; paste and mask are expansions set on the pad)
3_5MM_HOLE [mm]
  round 3.2 hole 3.5 unplated mask+0.102: ""(0,0)
3M_961102-6404-AR [mm] "Header, 2.54mm, 2x1, TH"
  rect 1.6x1.6 hole 1.1: 1(-1.27,0)
  round 1.6 hole 1.1: 2(1.27,0)
  silkscreen extent -2.52,-1.25 2.52,1.5, body extent -2.52,-1.25 2.52,1.25, height 8.5
5MM_HOLE [mm]
  round 4.7 hole 5 unplated mask+0.102: ""(0,0)
0402 [mm] "0402 from SM-752 data"
  rect 0.8x0.6 smd: 1(-0.6,0) 2(0.6,0)
  silkscreen extent -1.22,-0.52 1.22,0.52, body extent -0.55,-0.3 0.55,0.3, height 0.6
0402S [mil] "Based on C0402S footprint from PADS legacy"
  rect 15x24 smd: 1(-20,0) 2(20,0)
  body extent -22,-12 22,12, height 24
0603 [mm] "0603 from SM-752 data"
  rect 1x0.95 smd: 1(-0.8,0) 2(0.8,0)
  silkscreen extent -1.52,-0.69 1.52,0.69, body extent -0.87,-0.47 0.87,0.47, height 1
ADKOM_FH-1152P [mm] "TH, 44-Leads, Body 63x30.18mm"
  rrect50% 1.35x1.35 hole 0.9: 1(-15.24,26.67)
  round 1.35 hole 0.9: 2(-15.24,24.13) 3(-15.24,21.59) 4(-15.24,19.05) 5(-15.24,16.51) 6(-15.24,13.97) 7(-15.24,11.43) 8(-15.24,8.89) 9(-15.24,6.35) 10(-15.24,3.81) 11(-15.24,1.27) 12(-15.24,-1.27) 13(-15.24,-3.81) 14(-15.24,-6.35) 15(-15.24,-8.89) 16(-15.24,-11.43) 17(-15.24,-13.97) 18(-15.24,-16.51) 19(-15.24,-19.05) 20(-15.24,-21.59) 21(-15.24,-24.13) 22(-15.24,-26.67) 23(15.24,-26.67) 24(15.24,-24.13) 25(15.24,-21.59) 26(15.24,-19.05) 27(15.24,-16.51) 28(15.24,-13.97) 29(15.24,-11.43) 30(15.24,-8.89) 31(15.24,-6.35) 32(15.24,-3.81) 33(15.24,-1.27) 34(15.24,1.27) 35(15.24,3.81) 36(15.24,6.35) 37(15.24,8.89) 38(15.24,11.43) 39(15.24,13.97) 40(15.24,16.51) 41(15.24,19.05) 42(15.24,21.59) 43(15.24,24.13) 44(15.24,26.67)
  body extent -15.39,-31.5 15.39,32.5, height 3.1
CE_Mark_5mm [mil] "Minimum text height for CE Mark"
  silkscreen extent -138,-98 138,98
D0008A-MFG [mm]
  rrect17% 1.55x0.6 smd paste+0 mask+0: 1(-2.7,1.905) 2(-2.7,0.635) 3(-2.7,-0.635) 4(-2.7,-1.905) 5(2.7,-1.905) 6(2.7,-0.635) 7(2.7,0.635) 8(2.7,1.905)
  silkscreen extent -4.17,-2.5 1.5,2.5, body extent -3.57,-2.75 3.57,2.75, height 0.25
D0008B-MFG [mm]
  rrect17% 1.4x0.6 smd paste+0 mask+0: 1(-2.75,1.905) 2(-2.75,0.635) 3(-2.75,-0.635) 4(-2.75,-1.905) 5(2.75,-1.905) 6(2.75,-0.635) 7(2.75,0.635) 8(2.75,1.905)
  silkscreen extent -4.14,-2.5 1.5,2.5, body extent -3,-2.45 3,2.45, height 1.75
DBV0005A_N [mm] "SOT23, 5-Leads, Body 2.9x1.6mm, Pitch 0.95mm, Lead Span 2.8mm, IPC Medium Density"
  rrect17% 1x0.6 smd: 1(-1.375,0.95) 2(-1.375,0) 3(-1.375,-0.95) 4(1.375,-0.95) 5(1.375,0.95)
  silkscreen extent -1.63,-1.55 0.38,1.55, body extent -1.42,-1.46 1.42,1.46, height 1.09
DBV0006A-MFG [mm]
  rrect17% 1.1x0.6 smd paste+0 mask+0: 1(-1.3,0.95) 2(-1.3,0) 3(-1.3,-0.95) 4(1.3,-0.95) 5(1.3,0) 6(1.3,0.95)
  silkscreen extent -2.52,-1.53 0.35,1.53, body extent -1.95,-1.78 1.95,1.78, height 0.25
DW0016A-MFG [mm]
  rrect17% 2x0.6 smd paste+0 mask+0: 1(-4.65,4.445) 2(-4.65,3.175) 3(-4.65,1.905) 4(-4.65,0.635) 5(-4.65,-0.635) 6(-4.65,-1.905) 7(-4.65,-3.175) 8(-4.65,-4.445) 9(4.65,-4.445) 10(4.65,-3.175) 11(4.65,-1.905) 12(4.65,-0.635) 13(4.65,0.635) 14(4.65,1.905) 15(4.65,3.175) 16(4.65,4.445)
  silkscreen extent -6.32,-5.25 3.15,5.25, body extent -5.17,-5.15 5.16,5.15, height 2.6
Epcos_B72220S0271K101 [mm] "TH, 2-Leads, Dia 21.5mm, Pin Spacing 10mm"
  round 1.8 hole 1.3: 1(-5,1.15) 2(5,-1.15)
  silkscreen extent -10.75,-2.7 10.75,2.7, body extent -10.66,-2.7 10.75,2.7, height 25.48
Epson_FA-238 [mm] "SMD, 4-Leads, Body 3.2x2.5mm"
  rrect8% 1.2x1.4 smd: 1(-0.8,1.1) 2(-0.8,-1.1) 3(0.8,-1.1) 4(0.8,1.1)
  silkscreen extent -1.65,-2.05 1.65,2.05, body extent -1.3,-1.65 1.3,1.65, height 0.7
Fairchild_SOD-523F [mm] "SMD, 2-Leads, Body 1.2x0.8mm"
  rect 0.8x0.5 smd: 1(-1,0) 2(1,0)
  silkscreen extent -2.03,-0.65 1.4,0.65, body extent -0.65,-0.45 0.65,0.45, height 0.7
FCC_disclaimer [mil]
Fiducial10-30 [mm]
  round 1 smd mask+1: 1(0,0)
  Top Layer keep-out circle w1.678: c0,0 r0.75
FP-CGA2B2X7R1C224K050BE_0402-MFG [mm]
  rrect25% 0.4x0.5 smd paste+0 mask+0: 1(-0.4,0) 2(0.4,0)
  silkscreen extent -0.53,-0.63 0.53,0.63, body extent -0.7,-0.38 0.7,0.38, height 0.25
FP-CR0402-10W-000T_0402-MFG [mm]
  rrect17% 0.8x0.6 smd paste+0 mask+0: 1(-0.6,0) 2(0.6,0)
  silkscreen extent -0.53,-0.7 0.53,0.7, body extent -1.1,-0.4 1.1,0.4, height 0.25
IEC_HighVoltage_Large [mil]
  silkscreen extent -435,-352 435,401
IEC_HotSurface_Large [mil]
  silkscreen extent -435,-375 435,378
Keystone5000 [mil] "For Keystone 500x miniature loop terminals"
  round 80 hole 40: 1(0,0)
  silkscreen extent -52,-52 52,52, body extent -49,-49 49,49, height 182
Label_650x200 [mil] "Thermal Transfer Label"
  round 1 on Mech13: 0(0,0)
  silkscreen extent -325,-100 325,100, body extent -325,-100 325,100, height 1
Mill-Max_800-10-008-10-001000 [mm] "Mill-Max"
  rect 1.5x1.5 hole 0.85: 1(-8.89,0)
  round 1.5 hole 0.85: 2(-6.35,0) 3(-3.81,0) 4(-1.27,0) 5(1.27,0) 6(3.81,0) 7(6.35,0) 8(8.89,0)
  silkscreen extent -10.16,-1.27 10.16,1.78, body extent -10.16,-1.27 10.16,1.27, height 8.13
On-Shore_ED120_2DS [mm] "ONSHORE"
  rrect5% 2x2 hole 1.25: 1(-2.54,0)
  round 2 hole 1.25: 2(2.54,0)
  silkscreen extent -5.6,-4 5.12,5, body extent -5.78,-4 5.08,5, height 13
On-Shore_ED120_3DS [mm] "ONSHORE"
  rrect5% 2x2 hole 1.25: 1(-5.08,0)
  round 2 hole 1.25: 2(0,0) 3(5.08,0)
  silkscreen extent -8.14,-4 7.5,5, body extent -8.32,-4 7.62,5, height 13
On-Shore_OSTVN04A150 [mm] "Terminal Block, 2.54mm, 4-pole, Brass, TH"
  rect 1.8x1.8 hole 1.3: 1(-3.81,0)
  round 1.8 hole 1.3: 2(-1.27,0) 3(1.27,0) 4(3.81,0)
  silkscreen extent -5.8,-3.4 5.5,3.4, body extent -5.5,-3.25 5.47,3.38, height 8.91
PM0064A-MFG [mm]
  rrect33% 1.5x0.3 smd paste+0 mask+0: 1(-5.7,3.75) 2(-5.7,3.25) 3(-5.7,2.75) 4(-5.7,2.25) 5(-5.7,1.75) 6(-5.7,1.25) 7(-5.7,0.75) 8(-5.7,0.25) 9(-5.7,-0.25) 10(-5.7,-0.75) 11(-5.7,-1.25) 12(-5.7,-1.75) 13(-5.7,-2.25) 14(-5.7,-2.75) 15(-5.7,-3.25) 16(-5.7,-3.75) 33(5.7,-3.75) 34(5.7,-3.25) 35(5.7,-2.75) 36(5.7,-2.25) 37(5.7,-1.75) 38(5.7,-1.25) 39(5.7,-0.75) 40(5.7,-0.25) 41(5.7,0.25) 42(5.7,0.75) 43(5.7,1.25) 44(5.7,1.75) 45(5.7,2.25) 46(5.7,2.75) 47(5.7,3.25) 48(5.7,3.75)
  rrect33% 0.3x1.5 smd paste+0 mask+0: 17(-3.75,-5.7) 18(-3.25,-5.7) 19(-2.75,-5.7) 20(-2.25,-5.7) 21(-1.75,-5.7) 22(-1.25,-5.7) 23(-0.75,-5.7) 24(-0.25,-5.7) 25(0.25,-5.7) 26(0.75,-5.7) 27(1.25,-5.7) 28(1.75,-5.7) 29(2.25,-5.7) 30(2.75,-5.7) 31(3.25,-5.7) 32(3.75,-5.7) 49(3.75,5.7) 50(3.25,5.7) 51(2.75,5.7) 52(2.25,5.7) 53(1.75,5.7) 54(1.25,5.7) 55(0.75,5.7) 56(0.25,5.7) 57(-0.25,5.7) 58(-0.75,5.7) 59(-1.25,5.7) 60(-1.75,5.7) 61(-2.25,5.7) 62(-2.75,5.7) 63(-3.25,5.7) 64(-3.75,5.7)
  silkscreen extent -7.12,-5.1 5.1,5.1, body extent -6.55,-6.55 6.55,6.55, height 0.25
PM0064A_L [mm] "Thin QFP, 64-Leads, Body 10x10mm, Pitch 0.5mm, IPC High Density"
  oval 1.25x0.25 smd: 1(-5.625,3.75) 2(-5.625,3.25) 3(-5.625,2.75) 4(-5.625,2.25) 5(-5.625,1.75) 6(-5.625,1.25) 7(-5.625,0.75) 8(-5.625,0.25) 9(-5.625,-0.25) 10(-5.625,-0.75) 11(-5.625,-1.25) 12(-5.625,-1.75) 13(-5.625,-2.25) 14(-5.625,-2.75) 15(-5.625,-3.25) 16(-5.625,-3.75) 33(5.625,-3.75) 34(5.625,-3.25) 35(5.625,-2.75) 36(5.625,-2.25) 37(5.625,-1.75) 38(5.625,-1.25) 39(5.625,-0.75) 40(5.625,-0.25) 41(5.625,0.25) 42(5.625,0.75) 43(5.625,1.25) 44(5.625,1.75) 45(5.625,2.25) 46(5.625,2.75) 47(5.625,3.25) 48(5.625,3.75)
  oval 0.25x1.25 smd: 17(-3.75,-5.625) 18(-3.25,-5.625) 19(-2.75,-5.625) 20(-2.25,-5.625) 21(-1.75,-5.625) 22(-1.25,-5.625) 23(-0.75,-5.625) 24(-0.25,-5.625) 25(0.25,-5.625) 26(0.75,-5.625) 27(1.25,-5.625) 28(1.75,-5.625) 29(2.25,-5.625) 30(2.75,-5.625) 31(3.25,-5.625) 32(3.75,-5.625) 49(3.75,5.625) 50(3.25,5.625) 51(2.75,5.625) 52(2.25,5.625) 53(1.75,5.625) 54(1.25,5.625) 55(0.75,5.625) 56(0.25,5.625) 57(-0.25,5.625) 58(-0.75,5.625) 59(-1.25,5.625) 60(-1.75,5.625) 61(-2.25,5.625) 62(-2.75,5.625) 63(-3.25,5.625) 64(-3.75,5.625)
  silkscreen extent -5.65,-4.35 4.35,4.55, body extent -6.01,-6.01 6.01,6.01, height 1.5
Preci-dip_850-xx-004-10-001101 [mm] "Preci-dip"
  rect 1x1 hole 0.65: 1(-1.905,0)
  round 1 hole 0.65: 2(-0.635,0) 3(0.635,0) 4(1.905,0)
  silkscreen extent -3.33,-1.13 2.78,1.13, body extent -2.74,-1.1 2.74,1.1, height 5.2
PW0016A_L [mm] "TSOP, 16-Leads, Body 5x4.4mm, Pitch 0.65mm, IPC High Density"
  oval 1.2x0.4 smd: 1(-2.85,2.275) 2(-2.85,1.625) 3(-2.85,0.975) 4(-2.85,0.325) 5(-2.85,-0.325) 6(-2.85,-0.975) 7(-2.85,-1.625) 8(-2.85,-2.275) 9(2.85,-2.275) 10(2.85,-1.625) 11(2.85,-0.975) 12(2.85,-0.325) 13(2.85,0.325) 14(2.85,0.975) 15(2.85,1.625) 16(2.85,2.275)
  silkscreen extent -2,-2.55 1.85,2.55, body extent -3.21,-2.5 3.21,2.5, height 1
RSN0032B-MFG [mm]
  round 0.18 smd paste+0 mask+0: 1(-2.01,1.4) 2(-2.01,1) 3(-2.01,0.6) 4(-2.01,0.2) 5(-2,-0.2) 6(-2,-0.6) 7(-2,-1) 8(-2,-1.4) 9(-1.4,-2.01) 10(-1,-2.01) 11(-0.6,-2.01) 12(-0.2,-2.01) 13(0.2,-2) 14(0.6,-2) 15(1,-2) 16(1.4,-2) 17(2.01,-1.4) 18(2.01,-1) 19(2.01,-0.6) 20(2.01,-0.2) 21(2,0.2) 22(2,0.6) 23(2,1) 24(2,1.4) 25(1.4,2.01) 26(1,2.01) 27(0.6,2.01) 28(0.2,2.01) 29(-0.2,2) 30(-0.6,2) 31(-1,2) 32(-1.4,2)
  rrect4% 2.8x2.8 smd paste-1000 mask+0: 33(0,0)
  Top Layer region: -2.4,1.5 -1.7,1.5 -1.662,1.492 -1.629,1.471 -1.608,1.438 -1.6,1.4 -1.6,1.4 -1.613,1.35 -1.65,1.313 -1.7,1.3 -1.7,1.3 -2.4,1.3
  Top Layer region: -2.4,1.1 -1.7,1.1 -1.662,1.092 -1.629,1.071 -1.608,1.038 -1.6,1 -1.6,1 -1.613,0.95 -1.65,0.913 -1.7,0.9 -1.7,0.9 -2.4,0.9
  Top Layer region: -1.3,2.4 -1.3,1.7 -1.313,1.65 -1.35,1.613 -1.4,1.6 -1.4,1.6 -1.438,1.608 -1.471,1.629 -1.492,1.662 -1.5,1.7 -1.5,1.7 -1.5,2.4
  Top Layer region: -0.9,2.4 -0.9,1.7 -0.913,1.65 -0.95,1.613 -1,1.6 -1,1.6 -1.038,1.608 -1.071,1.629 -1.092,1.662 -1.1,1.7 -1.1,1.7 -1.1,2.4
  Top Layer region: -0.1,2.4 -0.1,1.7 -0.113,1.65 -0.15,1.613 -0.2,1.6 -0.2,1.6 -0.238,1.608 -0.271,1.629 -0.292,1.662 -0.3,1.7 -0.3,1.7 -0.3,2.4
  Top Layer region: -0.5,2.4 -0.5,1.7 -0.513,1.65 -0.55,1.613 -0.6,1.6 -0.6,1.6 -0.638,1.608 -0.671,1.629 -0.692,1.662 -0.7,1.7 -0.7,1.7 -0.7,2.4
  Top Layer region: 1.3,-2.4 1.3,-1.7 1.308,-1.662 1.329,-1.629 1.362,-1.608 1.4,-1.6 1.4,-1.6 1.438,-1.608 1.471,-1.629 1.492,-1.662 1.5,-1.7 1.5,-1.7 1.5,-2.4
  Top Layer region: 2.4,-1.5 1.7,-1.5 1.662,-1.492 1.629,-1.471 1.608,-1.438 1.6,-1.4 1.6,-1.4 1.608,-1.362 1.629,-1.329 1.662,-1.308 1.7,-1.3 1.7,-1.3 2.4,-1.3
  Top Layer region: 2.4,-1.1 1.7,-1.1 1.662,-1.092 1.629,-1.071 1.608,-1.038 1.6,-1 1.6,-1 1.608,-0.962 1.629,-0.929 1.662,-0.908 1.7,-0.9 1.7,-0.9 2.4,-0.9
  Top Layer region: 2.4,-0.7 1.7,-0.7 1.662,-0.692 1.629,-0.671 1.608,-0.638 1.6,-0.6 1.6,-0.6 1.608,-0.562 1.629,-0.529 1.662,-0.508 1.7,-0.5 1.7,-0.5 2.4,-0.5
  Top Layer region: 2.4,-0.3 1.7,-0.3 1.662,-0.292 1.629,-0.271 1.608,-0.238 1.6,-0.2 1.6,-0.2 1.608,-0.162 1.629,-0.129 1.662,-0.108 1.7,-0.1 1.7,-0.1 2.4,-0.1
  Top Layer region: 2.4,0.1 1.7,0.1 1.662,0.108 1.629,0.129 1.608,0.162 1.6,0.2 1.6,0.2 1.608,0.238 1.629,0.271 1.662,0.292 1.7,0.3 1.7,0.3 2.4,0.3
  Top Layer region: 2.4,0.9 1.7,0.9 1.662,0.908 1.629,0.929 1.608,0.962 1.6,1 1.6,1 1.608,1.038 1.629,1.071 1.662,1.092 1.7,1.1 1.7,1.1 2.4,1.1
  Top Layer region: 2.4,1.3 1.7,1.3 1.662,1.308 1.629,1.329 1.608,1.362 1.6,1.4 1.6,1.4 1.608,1.438 1.629,1.471 1.662,1.492 1.7,1.5 1.7,1.5 2.4,1.5
  Top Layer region: -2.4,-1.3 -1.7,-1.3 -1.662,-1.308 -1.629,-1.329 -1.608,-1.362 -1.6,-1.4 -1.6,-1.4 -1.613,-1.45 -1.65,-1.487 -1.7,-1.5 -1.7,-1.5 -2.4,-1.5
  Top Layer region: -2.4,-0.9 -1.7,-0.9 -1.662,-0.908 -1.629,-0.929 -1.608,-0.962 -1.6,-1 -1.6,-1 -1.613,-1.05 -1.65,-1.087 -1.7,-1.1 -1.7,-1.1 -2.4,-1.1
  Top Layer region: -2.4,-0.1 -1.7,-0.1 -1.662,-0.108 -1.629,-0.129 -1.608,-0.162 -1.6,-0.2 -1.6,-0.2 -1.613,-0.25 -1.65,-0.287 -1.7,-0.3 -1.7,-0.3 -2.4,-0.3
  Top Layer region: -2.4,-0.5 -1.7,-0.5 -1.662,-0.508 -1.629,-0.529 -1.608,-0.562 -1.6,-0.6 -1.6,-0.6 -1.613,-0.65 -1.65,-0.687 -1.7,-0.7 -1.7,-0.7 -2.4,-0.7
  Top Layer region: -2.4,0.3 -1.7,0.3 -1.662,0.292 -1.629,0.271 -1.608,0.238 -1.6,0.2 -1.6,0.2 -1.613,0.15 -1.65,0.113 -1.7,0.1 -1.7,0.1 -2.4,0.1
  Top Layer region: -2.4,0.7 -1.7,0.7 -1.662,0.692 -1.629,0.671 -1.608,0.638 -1.6,0.6 -1.6,0.6 -1.613,0.55 -1.65,0.513 -1.7,0.5 -1.7,0.5 -2.4,0.5
  Top Layer region: 0.1,-2.4 0.1,-1.7 0.108,-1.662 0.129,-1.629 0.162,-1.608 0.2,-1.6 0.2,-1.6 0.238,-1.608 0.271,-1.629 0.292,-1.662 0.3,-1.7 0.3,-1.7 0.3,-2.4
  Top Layer region: 1.5,2.4 1.5,1.7 1.487,1.65 1.45,1.613 1.4,1.6 1.4,1.6 1.362,1.608 1.329,1.629 1.308,1.662 1.3,1.7 1.3,1.7 1.3,2.4
  Top Layer region: 0.3,2.4 0.3,1.7 0.287,1.65 0.25,1.613 0.2,1.6 0.2,1.6 0.162,1.608 0.129,1.629 0.108,1.662 0.1,1.7 0.1,1.7 0.1,2.4
  Top Layer region: 0.9,-2.4 0.9,-1.7 0.908,-1.662 0.929,-1.629 0.962,-1.608 1,-1.6 1,-1.6 1.038,-1.608 1.071,-1.629 1.092,-1.662 1.1,-1.7 1.1,-1.7 1.1,-2.4
  Top Layer region: 1.1,2.4 1.1,1.7 1.087,1.65 1.05,1.613 1,1.6 1,1.6 0.962,1.608 0.929,1.629 0.908,1.662 0.9,1.7 0.9,1.7 0.9,2.4
  Top Layer region: 0.7,2.4 0.7,1.7 0.687,1.65 0.65,1.613 0.6,1.6 0.6,1.6 0.562,1.608 0.529,1.629 0.508,1.662 0.5,1.7 0.5,1.7 0.5,2.4
  Top Layer region: 0.5,-2.4 0.5,-1.7 0.508,-1.662 0.529,-1.629 0.562,-1.608 0.6,-1.6 0.6,-1.6 0.638,-1.608 0.671,-1.629 0.692,-1.662 0.7,-1.7 0.7,-1.7 0.7,-2.4
  Top Layer region: -0.3,-2.4 -0.3,-1.7 -0.292,-1.662 -0.271,-1.629 -0.238,-1.608 -0.2,-1.6 -0.2,-1.6 -0.162,-1.608 -0.129,-1.629 -0.108,-1.662 -0.1,-1.7 -0.1,-1.7 -0.1,-2.4
  Top Layer region: -0.7,-2.4 -0.7,-1.7 -0.692,-1.662 -0.671,-1.629 -0.638,-1.608 -0.6,-1.6 -0.6,-1.6 -0.562,-1.608 -0.529,-1.629 -0.508,-1.662 -0.5,-1.7 -0.5,-1.7 -0.5,-2.4
  Top Layer region: -1.1,-2.4 -1.1,-1.7 -1.092,-1.662 -1.071,-1.629 -1.038,-1.608 -1,-1.6 -1,-1.6 -0.962,-1.608 -0.929,-1.629 -0.908,-1.662 -0.9,-1.7 -0.9,-1.7 -0.9,-2.4
  Top Layer region: -1.5,-2.4 -1.5,-1.7 -1.492,-1.662 -1.471,-1.629 -1.438,-1.608 -1.4,-1.6 -1.4,-1.6 -1.362,-1.608 -1.329,-1.629 -1.308,-1.662 -1.3,-1.7 -1.3,-1.7 -1.3,-2.4
  Top Layer region: 2.4,0.5 1.7,0.5 1.662,0.508 1.629,0.529 1.608,0.562 1.6,0.6 1.6,0.6 1.608,0.638 1.629,0.671 1.662,0.692 1.7,0.7 1.7,0.7 2.4,0.7
  silkscreen extent -3.1,-2.07 2.07,2.07, body extent -2.5,-2.5 2.5,2.5, height 0.25
Samtec_FTSH-105-01-x-DV-K [mm] "Header(Shrouded), 1.27mm, 5x2, SMT"
  rect 2.79x0.74 smd: 1(-2.035,2.54) 2(2.035,2.54) 3(-2.035,1.27) 4(2.035,1.27) 5(-2.035,0) 6(2.035,0) 7(-2.035,-1.27) 8(2.035,-1.27) 9(-2.035,-2.54) 10(2.035,-2.54)
  silkscreen extent -3.73,-3.48 3.73,3.48, body extent -2.92,-3.18 2.92,3.17, height 6.13
SLR-342_Red [mm] "TH, 2-Leads, Dia 3.8mm, Lead Sapcing 2.5mm"
  rrect50% 2x2 hole 1: 1(-1.25,0)
  round 2 hole 1: 2(1.25,0)
  body extent -1.9,-1.9 1.9,1.9, height 6.35
Sullins_GRPB061VWVN-RC [mm] "SULLINS"
  rrect10% 1x1 hole 0.7: 1(-3.175,0)
  round 1 hole 0.7: 2(-1.905,0) 3(-0.635,0) 4(0.635,0) 5(1.905,0) 6(3.175,0)
  silkscreen extent -4.25,-1.17 3.93,1.22, body extent -3.85,-1.1 3.85,1.1, height 4.3
SW_1825264-1 [mm] "APEM"
  rect 1.5x1.5 hole 0.9: 1(-2.15,5)
  round 1.5 hole 0.9: 2(-2.15,3) 3(-2.15,1) 4(-2.15,-1) 5(-2.15,-3) 6(-2.15,-5) 7(2.15,-5) 8(2.15,-3) 9(2.15,-1) 10(2.15,1) 11(2.15,3) 12(2.15,5)
  round 2 hole 1.4: MH1(-4.4,6.5) MH2(-4.4,-6.5) MH3(4.4,-6.5) MH4(4.4,6.5)
  silkscreen extent -5.53,-7.6 4.8,7.5, body extent -4.7,-7.6 4.7,7.4, height 18
SW_MJTPSMWB [mm] "SMD, 4-Leads, Body 6.2x6.3mm, Pitch 4mm"
  rect 2.1x1.4 smd: 1(-4.45,2) 2(4.45,2) 3(-4.45,-2) 4(4.45,-2)
  silkscreen extent -4.57,-3.15 3.1,3.37, body extent -4.5,-3.15 4.5,3.15, height 3.8
TE_2-5747706-0 [mil] "Receptacle, D-SUB-9, 2.74mm, TH"
  rrect50% 61.5x61.5 hole 41: 1(216,56)
  round 61.5 hole 41: 2(108,56) 3(0,56) 4(-108,56) 5(-216,56) 6(162,-56) 7(54,-56) 8(-54,-56) 9(-162,-56)
  round 181.5 hole 121: 10(492,0) 11(-492,0)
  body extent -606,-248 607,248, height 479
TSW-103-07-G-S [mm] "Samtec 100mil, 1x3, 230 mil above insulator"
  rrect50% 1.65x1.65 hole 1.016: 1(-2.54,0)
  round 1.65 hole 1.016: 2(0,0) 3(2.54,0)
  body extent -3.81,-1.27 3.81,1.27, height 8.38
WEEE_Minimum [mil] "WEEElie bin"
  silkscreen extent -95,-172 99,104
WURTH_61300411121 [mm] "Header, 2.54mm, 4x1, TH"
  rrect50% 1.65x1.65 hole 1.15: 1(-3.81,0)
  round 1.65 hole 1.15: 2(-1.27,0) 3(1.27,0) 4(3.81,0)
  body extent -5.08,-1.27 5.08,1.27, height 8.54
WURTH_61300611121 [mm] "Header, 2.54mm, 6x1, TH"
  rrect50% 1.65x1.65 hole 1.15: 1(-6.35,0)
  round 1.65 hole 1.15: 2(-3.81,0) 3(-1.27,0) 4(1.27,0) 5(3.81,0) 6(6.35,0)
  body extent -7.62,-1.27 7.62,1.27, height 8.54
Wurth_61301421121 [mm] "Header, 2.54mm, 7x2, TH"
  rrect50% 1.65x1.65 hole 1.1: 1(-1.27,7.62)
  round 1.65 hole 1.1: 2(1.27,7.62) 3(-1.27,5.08) 4(1.27,5.08) 5(-1.27,2.54) 6(1.27,2.54) 7(-1.27,0) 8(1.27,0) 9(-1.27,-2.54) 10(1.27,-2.54) 11(-1.27,-5.08) 12(1.27,-5.08) 13(-1.27,-7.62) 14(1.27,-7.62)
  body extent -2.54,-8.89 2.54,8.89, height 8.55

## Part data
C1 C3 C7 C9 C10 C12 C13 C15 C16 C18 C19 C21 C45 C47 C49: library part CMP-0084283-1, "CAP, CERM, 10 pF, 100 V,+/- 5%, C0G/NP0, AEC-Q200 Grade 1, 0603", Cap_Case=0603, Manufacturer=MuRata, TempCo=C0G/NP0, Tolerance_%=5%, Value2=100V, ValueDisplayed=10pF
C2 C8 C11: library part CMP-0084514-1, "CAP, CERM, 6800 pF, 100 V,+/- 5%, C0G/NP0, AEC-Q200 Grade 0, 0603", Cap_Case=0603, Manufacturer=TDK, TempCo=C0G/NP0, Tolerance_%=5%, Value2=100V, ValueDisplayed=6800pF
C4: library part CMP-0092769-1, "Cap Ceramic 220nF 16V X7R 10% Pad SMD 0402 +125°C Automotive T/R", Manufacturer="TDK Corporation", Operating Temperature Range="-55°C to +125°C", TempCo=15%, Temperature Characteristic=X7R, Tolerance_%=0.1%, ValueDisplayed=220nF
C5 C6: library part CMP-0079607-1, "CAP, CERM, 1 µF, 16 V,+/- 10%, X7R, AEC-Q200 Grade 1, 0603", Cap_Case=0603, Manufacturer=TDK, Supplier Part Number 1=445-12539-1-ND, TempCo=X7R, Tolerance_%=10%, Value2=16V, ValueDisplayed=1µF
C14 C17 C20 C48: library part CMP-0007487-4, "CAP, CERM, 6800 pF, 100 V, +/- 10%, X7R, 0603", Cap_Case=0603, Manufacturer=MuRata, PartNumber=GRM188R72A682KA01D, Supplier Part Number 1=GRM188R72A682KA01D-ND, TempCo=X7R, Tolerance_%=10%, Value1=Unknown, Value2=100V, ValueDisplayed=6800pF
C22: library part CMP-0007328-5, "CAP, CERM, 0.47 uF, 10 V, +/- 10%, X5R, 0603", Cap_Case=0603, Manufacturer=MuRata, Supplier Part Number 1=490-1539-1-ND, TempCo=X5R, Tolerance_%=10%, Value1=Unknown, Value2=10V, ValueDisplayed=0.47uF
C23: library part CMP-0086193-1, "CAP, CERM, 10 µF, 10 V,+/- 10%, X5R, 0603", Cap_Case=0603, Manufacturer=MuRata, TempCo=X5R, Tolerance_%=10%, Value2=10V, ValueDisplayed=10µF
C24: library part CMP-0006560-2, "CAP, CERM, 1000 pF, 10 V, +/- 10%, X5R, 0402", Cap_Case=0402, Manufacturer=MuRata, Supplier Part Number 1=GRM155R61A102KA01D-ND, TempCo=X5R, Tolerance_%=10%, Value1=Unknown, Value2=10V, ValueDisplayed=1000pF
C25: library part CMP-0007393-1, "CAP, CERM, 0.33 uF, 16 V, +/- 10%, X7R, 0603", Cap_Case=0603, Manufacturer=MuRata, Supplier Part Number 1=490-3294-1-ND, TempCo=X7R, Tolerance_%=10%, Value1=Unknown, Value2=16V, ValueDisplayed=0.33uF
C26: library part CMP-0006356-2, "CAP, CERM, 0.1 uF, 50 V, +/- 10%, X7R, AEC-Q200 Grade 1, 0402", Cap_Case=0402, Manufacturer=MuRata, Supplier Part Number 1=490-10672-1-ND, TempCo=X7R, Tolerance_%=10%, Value1=Unknown, Value2=50V, ValueDisplayed=0.1uF
C27 C28: library part CMP-0006420-2, "CAP, CERM, 15 pF, 50 V, +/- 5%, C0G/NP0, 0402", Cap_Case=0402, Manufacturer=MuRata, Supplier Part Number 1=81-GRM1555C1H150JA1D, TempCo=C0G/NP0, Tolerance_%=5%, Value1=Unknown, Value2=50V, ValueDisplayed=15pF
C29 C32 C33 C36 C37 C39 C43 C44: library part CMP-0007090-4, "CAP, CERM, 0.1 uF, 25 V, +/- 10%, X8R, AEC-Q200 Grade 0, 0603", Cap_Case=0603, Manufacturer=TDK, Supplier Part Number 1=445-5885-1-ND, TempCo=X8R, Tolerance_%=10%, Value1=Unknown, Value2=25V, ValueDisplayed=0.1uF
C30 C50: library part CMP-0007502-5, "CAP, CERM, 2.2 uF, 50 V, +/- 10%, X5R, AEC-Q200 Grade 3, 0603", Cap_Case=0603, Manufacturer=MuRata, Supplier Part Number 1=490-12332-1-ND, TempCo=X5R, Tolerance_%=10%, Value1=Unknown, Value2=50V, ValueDisplayed=2.2uF
C31 C34 C41 C46: library part CMP-0006979-5, "CAP, CERM, 0.1 uF, 25 V, +/- 10%, X7R, 0603", Cap_Case=0603, Manufacturer=Kemet, Supplier Part Number 1=399-5345-1-ND, TempCo=X7R, Tolerance_%=10%, Value1=Unknown, Value2=25V, ValueDisplayed=0.1uF
C35: library part CMP-0082113-1, "CAP, CERM, 1 µF, 25 V,+/- 20%, X7R, AEC-Q200 Grade 1, 0603", Cap_Case=0603, Manufacturer=TDK, Supplier Part Number 1=445-12548-2-ND, TempCo=X7R, Tolerance_%=20%, Value2=25V, ValueDisplayed=1µF
C38 C40: library part CMP-0007069-4, "CAP, CERM, 10 pF, 50 V, +/- 5%, C0G/NP0, AEC-Q200 Grade 1, 0603", Cap_Case=0603, Manufacturer=TDK, Supplier Part Number 1=445-5628-1-ND, TempCo=C0G/NP0, Tolerance_%=5%, Value1=Unknown, Value2=50V, ValueDisplayed=10pF
C42 C51: library part CMP-0006867-4, "CAP, CERM, 1 uF, 25 V, +/- 10%, X7R, 0603", Cap_Case=0603, Manufacturer=Kemet, Supplier Part Number 1=399-7376-1-ND, TempCo=X7R, Tolerance_%=10%, Value1=Unknown, Value2=25V, ValueDisplayed=1uF
C52 C53 C54 C55 C57: library part CMP-0006350-2, "CAP, CERM, 0.1 uF, 10 V, +/- 10%, X7R, AEC-Q200 Grade 1, 0402", Cap_Case=0402, Manufacturer=MuRata, Supplier Part Number 1=81-GCM155R71A104K5D, TempCo=X7R, Tolerance_%=10%, Value1=Unknown, Value2=10V, ValueDisplayed=0.1uF
C56: library part CMP-0007318-5, "CAP, CERM, 10 uF, 10 V, +/- 20%, X5R, 0603", Cap_Case=0603, Manufacturer=MuRata, TempCo=X5R, Tolerance_%=20%, Value1=Unknown, Value2=10V, ValueDisplayed=10uF
C58: library part CMP-0006229-2, "CAP, CERM, 1000 pF, 25 V, +/- 10%, X7R, 0402", Cap_Case=0402, Manufacturer="Wurth Elektronik", Supplier Part Number 1=710-885012205044, TempCo=X7R, Tolerance_%=10%, Value1=Unknown, Value2=25V, ValueDisplayed=1000pF
C59 C60: library part CMP-0006237-2, "CAP, CERM, 0.1 uF, 16 V, +/- 10%, X7R, AEC-Q200 Grade 1, 0402", Cap_Case=0402, Manufacturer=Kemet, Supplier Part Number 1=399-6828-1-ND, TempCo=X7R, Tolerance_%=10%, Value1=Unknown, Value2=16V, ValueDisplayed=0.1uF
D1 D2: library part CMP-0079280-1, "LED, Red, TH", Color=Red, Manufacturer=Rohm, Power_TotalModule=60mW, Supplier Part Number 1=511-1249-ND, Value1=0.06W, Value2=2V
D3 D4 D5: library part CMP-0076982-2, "Diode, Switching, 75 V, 0.3 A, SOD-523F", Manufacturer="Fairchild Semiconductor", Value1=0.3A, Value2=V
FID1 FID2 FID3: library part CMP-0077181-1, "Fiducial mark.  There is nothing to buy or mount.", Manufacturer=N/A
H13 H14 H15 H16: library part CMP-0079337-1, "5 mm PCB Hole", Manufacturer=Any
H_IA1 H_IA2 H_IB1 H_IB2 H_IC1 H_IC2: library part CMP-0079299-1, "3.5 mm PCB Hole", Manufacturer=Any
J1 J2 J3: library part CMP-0074910-1, "Terminal Block, 5.08 mm, 2x1, Brass, TH", Color=Blue, Current_A=15A, Manufacturer="On-Shore Technology", Supplier Part Number 1=ED1609-ND, Voltage_V=300V
J4 J5 J6 J15: library part CMP-0074911-1, "Terminal Block, 5.08 mm, 3x1, Brass, TH", Color=Blue, Current_A=15A, Manufacturer="On-Shore Technology", Supplier Part Number 1=ED1610-ND, Voltage_V=300V
J7 J8: library part CMP-0075197-1, "Header, 2.54mm, 2x1, TH", Color=Black, Current_A=2A, Manufacturer=3M, Supplier Part Number 1=3M9447-ND, Voltage_V=1kV
J9: library part CMP-0075634-2, "Header(Shrouded), 1.27mm, 5x2, Gold, SMT", Color=Black, Current_A=3.3A, Manufacturer=Samtec, Supplier Part Number 1=SAM8799-ND
J10: library part CMP-0054801-2, "Header, 2.54 mm, 6x1, Gold, TH", Color=Black, Manufacturer="Wurth Elektronik", Supplier Part Number 1=732-5319-ND
J11: library part CMP-0055090-1, "Header, 100mil, 8x1, TH", Manufacturer=Mill-Max, Supplier Part Number 1=ED7208-ND
J12: library part CMP-0075095-1, "Terminal Block, 2.54mm, 4x1, Brass, TH", Manufacturer="On-Shore Technology", Supplier Part Number 1=ED10563-ND
J13: library part CMP-0086014-1, "Header, 2.54mm, 7x2, Gold, TH", Color=Black, Current_A=3A, Manufacturer="Wurth Elektronik", Voltage_V=250V
J14: library part CMP-0054798-2, "Header, 2.54 mm, 4x1, Gold, TH", Color=Black, Manufacturer="Wurth Elektronik", Supplier Part Number 1=732-5317-ND
J16: library part CMP-0074999-1, "Header, 50mil, 4x1, Gold, TH", Manufacturer=Preci-Dip, Supplier Part Number 1=1212-1328-ND
J17 J18: library part CMP-0054561-1, "Header, 50mil, 6x1, Gold,  TH", Manufacturer="Sullins Connector Solutions", Supplier Part Number 1=S9014E-06-ND
JP1 JP2: library part CMP-0075407-2, "Header, 100mil, 3x1, Gold, TH", Color=Black, Current_A=6.3A, Manufacturer=Samtec, Supplier Part Number 1=SAM1029-03-ND, Voltage_V=550V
